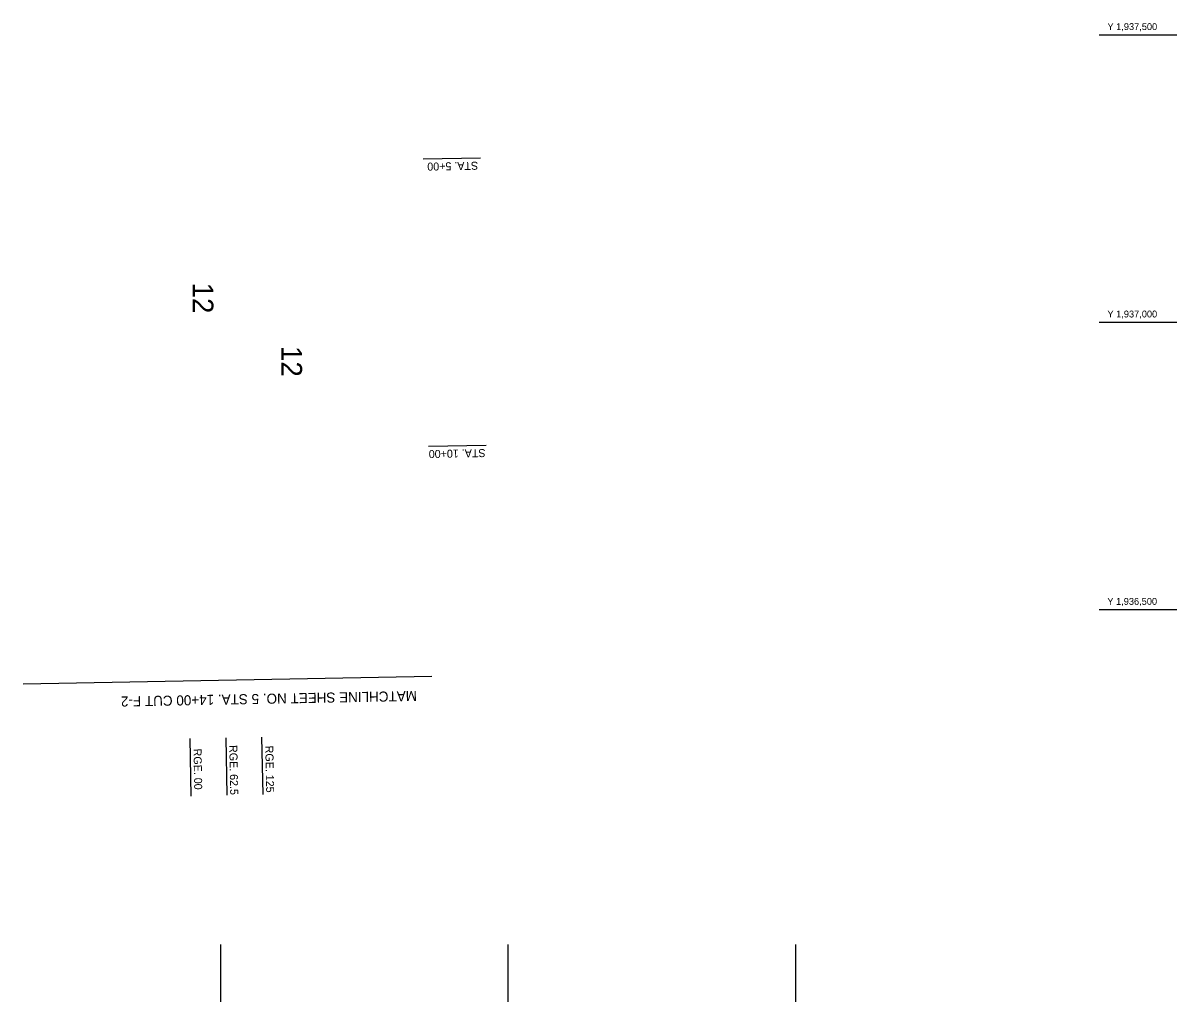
# Model space of a CAD drawing. Extents: x 585464 to 588664, y 1935616 to 1939717.
# Drawn here: x 586657 to 588664, y 1935817 to 1937520 of the extents above; entities that cross this region are included whole.
import ezdxf

# ---------------------------------------------------------------- set-up
doc = ezdxf.new("R2010")
doc.units = 0
for name, color, linetype in [('V-ANNO-KEYN', 7, 'Continuous'), ('V-ANNO-MASK', 7, 'Continuous'), ('V-ANNO-NOTE', 7, 'Continuous'), ('V-ANNO-NPLT', 7, 'Continuous'), ('V-ANNO-PATT', 7, 'Continuous'), ('V-ANNO-TEXT', 7, 'Continuous')]:
    doc.layers.add(name, color=color, linetype=linetype)

msp = doc.modelspace()

# ---------------------------------------------------------------- linework, layer by layer
at = {"layer": 'V-ANNO-NOTE'}
msp.add_line((587367.8, 1936383.4), (586656.6, 1936369.9), dxfattribs=at)
at = {"layer": 'V-ANNO-NPLT'}
for p, q in [((587452.5, 1937285.2), (587352.5, 1937283.3)), ((587462, 1936785.3), (587362, 1936783.4))]:
    msp.add_line(p, q, dxfattribs=at)
at = {"layer": 'V-ANNO-PATT'}
for p, q in [((586946.6, 1936275.4), (586948.5, 1936175.4)), ((587009.1, 1936276.6), (587011, 1936176.6)), ((587071.6, 1936277.7), (587073.5, 1936177.8))]:
    msp.add_line(p, q, dxfattribs=at)
at = {"layer": 'V-ANNO-TEXT'}
for p, q in [((588528.7, 1937500), (588663.7, 1937500)), ((588528.7, 1937000), (588663.7, 1937000)), ((588528.7, 1936500), (588663.7, 1936500)), ((587000, 1935917.1), (587000, 1935817.1)), ((587500, 1935917.1), (587500, 1935817.1)), ((588000, 1935917.1), (588000, 1935817.1))]:
    msp.add_line(p, q, dxfattribs=at)

# ---------------------------------------------------------------- texts
at = {"layer": 'V-ANNO-KEYN'}
for s, p in [('Y 1,937,500', (588542.8, 1937508)), ('Y 1,937,000', (588542.8, 1937008)), ('Y 1,936,500', (588542.6, 1936508))]:
    msp.add_text(s, height=12, dxfattribs=at).set_placement(p)
at = {"layer": 'V-ANNO-MASK'}
msp.add_text('MATCHLINE SHEET NO. 5 STA. 14+00 CUT F-2', height=17.52, rotation=181.0918, dxfattribs=at).set_placement((587341.5, 1936358.3))
at = {"layer": 'V-ANNO-NPLT'}
for s, p in [('STA. 5+00', (587448, 1937279)), ('STA. 10+00', (587460.9, 1936779.1))]:
    msp.add_text(s, height=13.92, rotation=181.0918, dxfattribs=at).set_placement(p)
at = {"layer": 'V-ANNO-PATT'}
for s, height, rotation, p in [('12', 36, 270, (586951.6, 1937068.6)), ('12', 36, 270, (587105.9, 1936958.3)), ('RGE. 00', 13.92, 271.0918, (586953, 1936257.7)), ('RGE. 62.5', 13.92, 271.0918, (587015.3, 1936264)), ('RGE. 125', 13.92, 271.0918, (587077.9, 1936262.9))]:
    msp.add_text(s, height=height, rotation=rotation, dxfattribs=at).set_placement(p)

doc.saveas('drawing.dxf')
